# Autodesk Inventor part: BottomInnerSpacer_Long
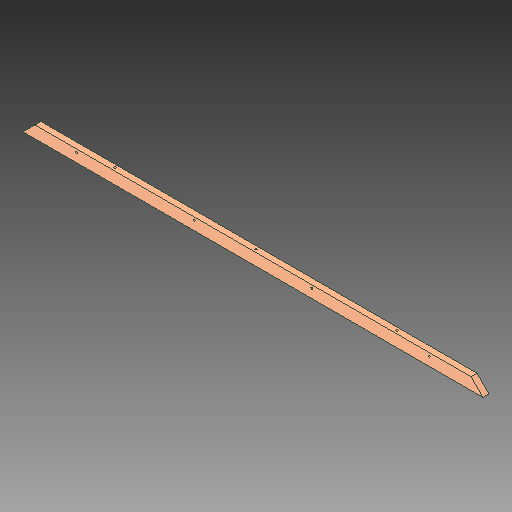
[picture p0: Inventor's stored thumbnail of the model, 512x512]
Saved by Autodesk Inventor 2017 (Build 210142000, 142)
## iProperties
Created: 2017-05
Part Number: BottomInnerSpacer_Long
Material: Generic
Document SubType Name: Modeling
Designer: Savy
Density: 1 g/cm^3
Appearance: Default
Author: Savy
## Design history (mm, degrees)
feature "SOLID1"
body "Solid1"
